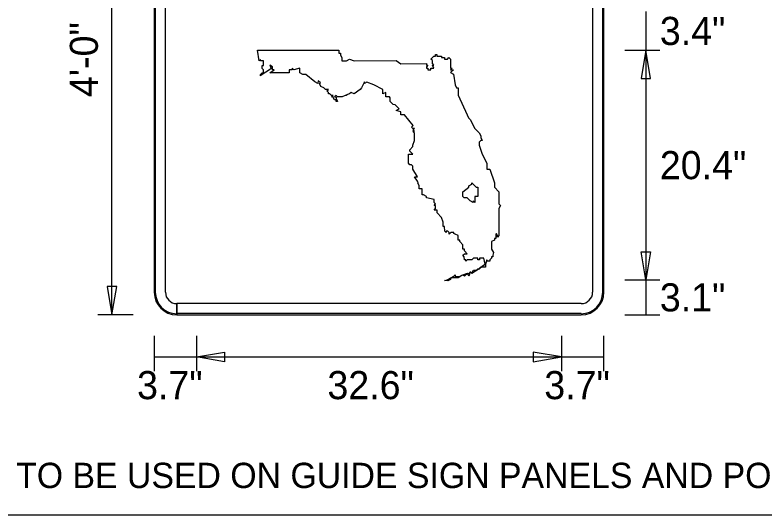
# Model space of a CAD drawing. Extents: x 17890628 to 17890844, y 17897693 to 17898031.
# Drawn here: x 17890808.4 to 17890826.19, y 17897976.3 to 17897988.15 of the extents above; entities that cross this region are included whole.
import ezdxf

# ---------------------------------------------------------------- set-up
doc = ezdxf.new("R2010")
doc.units = 0
for name, color, linetype in [('GSColorFill', 7, 'Continuous'), ('GSDims', 7, 'Continuous'), ('SheetLinesMisc2_dp', 7, 'Continuous')]:
    doc.layers.add(name, color=color, linetype=linetype)

msp = doc.modelspace()

# ---------------------------------------------------------------- linework, layer by layer
at = {"layer": 'GSColorFill'}
for p, q in [((17890811.701, 17897993.312), (17890811.701, 17897981.578)), ((17890811.701, 17897993.312), (17890811.701, 17897981.578)), ((17890811.701, 17897993.312), (17890811.701, 17897981.578)), ((17890811.728, 17897981.578), (17890811.728, 17897993.312)), ((17890811.968, 17897981.578), (17890811.968, 17897993.312)), ((17890822.101, 17897993.312), (17890822.101, 17897981.578)), ((17890822.341, 17897993.312), (17890822.341, 17897981.578)), ((17890822.368, 17897981.578), (17890822.368, 17897993.312)), ((17890822.368, 17897981.578), (17890822.368, 17897993.312)), ((17890822.368, 17897981.578), (17890822.368, 17897993.312)), ((17890814.153, 17897987.316), (17890816.084, 17897987.318)), ((17890814.189, 17897987.065), (17890814.153, 17897987.316)), ((17890816.084, 17897987.318), (17890816.085, 17897987.247)), ((17890816.085, 17897987.247), (17890816.12, 17897987.246)), ((17890816.12, 17897987.246), (17890816.12, 17897987.211)), ((17890816.12, 17897987.211), (17890816.156, 17897987.139)), ((17890818.266, 17897987.105), (17890818.337, 17897987.177)), ((17890818.337, 17897987.177), (17890818.373, 17897987.177)), ((17890818.373, 17897987.177), (17890818.373, 17897987.213)), ((17890818.373, 17897987.213), (17890818.409, 17897987.213)), ((17890818.409, 17897987.213), (17890818.409, 17897987.177)), ((17890818.409, 17897987.177), (17890818.516, 17897987.177)), ((17890818.516, 17897987.177), (17890818.516, 17897987.142)), ((17890814.225, 17897987.101), (17890814.189, 17897987.065)), ((17890814.224, 17897987.065), (17890814.225, 17897987.101)), ((17890814.296, 17897987.066), (17890814.224, 17897987.065)), ((17890814.296, 17897986.958), (17890814.296, 17897987.066)), ((17890816.156, 17897987.139), (17890816.156, 17897987.068)), ((17890816.156, 17897987.068), (17890816.263, 17897987.068)), ((17890816.263, 17897987.068), (17890816.335, 17897987.104)), ((17890816.335, 17897987.104), (17890816.443, 17897987.068)), ((17890816.443, 17897987.068), (17890817.444, 17897987.07)), ((17890817.444, 17897987.07), (17890817.55, 17897986.998)), ((17890817.55, 17897986.998), (17890818.159, 17897986.999)), ((17890818.159, 17897986.999), (17890818.159, 17897986.963)), ((17890818.302, 17897987.07), (17890818.266, 17897987.105)), ((17890818.302, 17897986.999), (17890818.302, 17897987.07)), ((17890818.337, 17897986.963), (17890818.302, 17897986.999)), ((17890818.516, 17897987.142), (17890818.588, 17897987.142)), ((17890818.588, 17897987.142), (17890818.588, 17897987.106)), ((17890818.588, 17897987.106), (17890818.659, 17897987.106)), ((17890818.659, 17897987.106), (17890818.695, 17897987.142)), ((17890818.695, 17897987.142), (17890818.731, 17897987.106)), ((17890818.731, 17897987.106), (17890818.731, 17897986.892)), ((17890814.261, 17897986.887), (17890814.26, 17897986.958)), ((17890814.26, 17897986.958), (17890814.296, 17897986.958)), ((17890814.297, 17897986.851), (17890814.261, 17897986.887)), ((17890814.439, 17897986.851), (17890814.261, 17897986.743)), ((17890814.297, 17897986.78), (17890814.297, 17897986.851)), ((17890814.475, 17897986.886), (17890814.439, 17897986.851)), ((17890814.51, 17897986.923), (17890814.44, 17897986.959)), ((17890814.44, 17897986.959), (17890814.475, 17897986.886)), ((17890814.44, 17897986.78), (17890814.547, 17897986.851)), ((17890814.511, 17897986.851), (17890814.51, 17897986.923)), ((17890814.547, 17897986.851), (17890814.511, 17897986.851)), ((17890814.976, 17897986.852), (17890814.904, 17897986.851)), ((17890814.904, 17897986.851), (17890814.905, 17897986.779)), ((17890815.012, 17897986.851), (17890814.976, 17897986.888)), ((17890814.976, 17897986.888), (17890814.976, 17897986.852)), ((17890815.155, 17897986.888), (17890815.012, 17897986.851)), ((17890815.155, 17897986.78), (17890815.155, 17897986.888)), ((17890818.159, 17897986.963), (17890818.195, 17897986.963)), ((17890818.195, 17897986.963), (17890818.159, 17897986.927)), ((17890818.159, 17897986.927), (17890818.159, 17897986.891)), ((17890818.159, 17897986.891), (17890818.195, 17897986.891)), ((17890818.195, 17897986.891), (17890818.194, 17897986.855)), ((17890818.194, 17897986.855), (17890818.266, 17897986.856)), ((17890818.266, 17897986.856), (17890818.266, 17897986.891)), ((17890818.266, 17897986.891), (17890818.337, 17897986.891)), ((17890818.337, 17897986.891), (17890818.302, 17897986.964)), ((17890818.302, 17897986.964), (17890818.337, 17897986.963)), ((17890818.731, 17897986.892), (17890818.767, 17897986.891)), ((17890818.767, 17897986.891), (17890818.731, 17897986.856)), ((17890818.731, 17897986.856), (17890818.803, 17897986.856)), ((17890818.803, 17897986.856), (17890818.731, 17897986.785)), ((17890814.225, 17897986.744), (17890814.261, 17897986.779)), ((17890814.225, 17897986.708), (17890814.225, 17897986.744)), ((17890814.261, 17897986.743), (17890814.225, 17897986.708)), ((17890814.261, 17897986.779), (17890814.297, 17897986.78)), ((17890814.905, 17897986.779), (17890814.44, 17897986.78)), ((17890815.227, 17897986.745), (17890815.155, 17897986.78)), ((17890815.298, 17897986.745), (17890815.227, 17897986.745)), ((17890815.513, 17897986.567), (17890815.298, 17897986.745)), ((17890818.731, 17897986.785), (17890818.803, 17897986.749)), ((17890818.803, 17897986.749), (17890818.839, 17897986.499)), ((17890815.585, 17897986.53), (17890815.513, 17897986.567)), ((17890815.588, 17897986.591), (17890815.585, 17897986.53)), ((17890815.644, 17897986.542), (17890815.588, 17897986.591)), ((17890815.62, 17897986.53), (17890815.644, 17897986.542)), ((17890815.656, 17897986.459), (17890815.62, 17897986.53)), ((17890815.728, 17897986.423), (17890815.656, 17897986.459)), ((17890816.693, 17897986.567), (17890816.622, 17897986.425)), ((17890816.693, 17897986.531), (17890816.693, 17897986.567)), ((17890816.744, 17897986.558), (17890816.693, 17897986.531)), ((17890816.908, 17897986.497), (17890816.744, 17897986.558)), ((17890817.123, 17897986.389), (17890816.908, 17897986.497)), ((17890818.839, 17897986.499), (17890818.875, 17897986.427)), ((17890815.763, 17897986.387), (17890815.728, 17897986.423)), ((17890815.834, 17897986.388), (17890815.763, 17897986.387)), ((17890815.799, 17897986.352), (17890815.834, 17897986.388)), ((17890815.835, 17897986.316), (17890815.799, 17897986.352)), ((17890815.836, 17897986.281), (17890815.835, 17897986.316)), ((17890815.87, 17897986.28), (17890815.836, 17897986.281)), ((17890815.907, 17897986.245), (17890815.87, 17897986.28)), ((17890816.336, 17897986.281), (17890816.264, 17897986.257)), ((17890816.371, 17897986.317), (17890816.336, 17897986.281)), ((17890816.443, 17897986.281), (17890816.371, 17897986.317)), ((17890816.587, 17897986.389), (17890816.443, 17897986.281)), ((17890816.622, 17897986.425), (17890816.587, 17897986.389)), ((17890817.123, 17897986.283), (17890817.123, 17897986.389)), ((17890817.194, 17897986.318), (17890817.123, 17897986.283)), ((17890817.194, 17897986.211), (17890817.194, 17897986.318)), ((17890818.875, 17897986.427), (17890818.911, 17897986.427)), ((17890818.911, 17897986.427), (17890818.911, 17897986.248)), ((17890815.906, 17897986.209), (17890815.943, 17897986.245)), ((17890815.942, 17897986.209), (17890815.906, 17897986.209)), ((17890815.943, 17897986.245), (17890815.907, 17897986.245)), ((17890815.979, 17897986.138), (17890815.942, 17897986.209)), ((17890816.014, 17897986.244), (17890815.978, 17897986.209)), ((17890815.978, 17897986.209), (17890816.014, 17897986.208)), ((17890816.014, 17897986.137), (17890815.979, 17897986.138)), ((17890816.049, 17897986.209), (17890816.014, 17897986.244)), ((17890816.014, 17897986.208), (17890816.014, 17897986.173)), ((17890816.014, 17897986.173), (17890816.049, 17897986.102)), ((17890816.014, 17897986.105), (17890816.014, 17897986.137)), ((17890816.049, 17897986.102), (17890816.014, 17897986.105)), ((17890816.157, 17897986.21), (17890816.049, 17897986.209)), ((17890816.229, 17897986.245), (17890816.157, 17897986.21)), ((17890816.265, 17897986.245), (17890816.229, 17897986.245)), ((17890816.264, 17897986.257), (17890816.265, 17897986.245)), ((17890817.285, 17897986.21), (17890817.194, 17897986.211)), ((17890817.302, 17897986.191), (17890817.285, 17897986.21)), ((17890817.302, 17897986.103), (17890817.302, 17897986.191)), ((17890817.374, 17897986.032), (17890817.302, 17897986.103)), ((17890818.911, 17897986.248), (17890819.126, 17897985.784)), ((17890817.418, 17897986.024), (17890817.374, 17897986.032)), ((17890817.516, 17897985.925), (17890817.418, 17897986.024)), ((17890817.445, 17897985.888), (17890817.516, 17897985.925)), ((17890817.552, 17897985.853), (17890817.445, 17897985.888)), ((17890817.552, 17897985.782), (17890817.552, 17897985.853)), ((17890817.638, 17897985.782), (17890817.552, 17897985.782)), ((17890817.841, 17897985.534), (17890817.638, 17897985.782)), ((17890819.126, 17897985.784), (17890819.161, 17897985.712)), ((17890819.161, 17897985.712), (17890819.198, 17897985.676)), ((17890819.198, 17897985.676), (17890819.306, 17897985.462)), ((17890817.803, 17897985.496), (17890817.841, 17897985.534)), ((17890817.838, 17897985.461), (17890817.803, 17897985.496)), ((17890817.873, 17897985.459), (17890817.838, 17897985.461)), ((17890817.839, 17897985.425), (17890817.873, 17897985.459)), ((17890817.875, 17897985.389), (17890817.839, 17897985.425)), ((17890817.875, 17897985.353), (17890817.839, 17897985.389)), ((17890817.839, 17897985.389), (17890817.845, 17897985.388)), ((17890817.845, 17897985.388), (17890817.875, 17897985.389)), ((17890819.306, 17897985.462), (17890819.413, 17897985.355)), ((17890817.875, 17897985.174), (17890817.875, 17897985.353)), ((17890819.413, 17897985.355), (17890819.448, 17897985.284)), ((17890819.448, 17897985.284), (17890819.448, 17897985.247)), ((17890819.448, 17897985.247), (17890819.484, 17897985.176)), ((17890817.768, 17897984.959), (17890817.84, 17897985.031)), ((17890817.839, 17897985.066), (17890817.875, 17897985.174)), ((17890817.84, 17897985.031), (17890817.839, 17897985.066)), ((17890819.449, 17897985.176), (17890819.412, 17897985.14)), ((17890819.412, 17897985.14), (17890819.412, 17897985.069)), ((17890819.412, 17897985.069), (17890819.485, 17897984.854)), ((17890819.484, 17897985.176), (17890819.449, 17897985.176)), ((17890817.733, 17897984.638), (17890817.732, 17897984.852)), ((17890817.732, 17897984.852), (17890817.84, 17897984.852)), ((17890817.768, 17897984.924), (17890817.768, 17897984.959)), ((17890817.84, 17897984.852), (17890817.768, 17897984.924)), ((17890819.485, 17897984.854), (17890819.592, 17897984.64)), ((17890817.768, 17897984.601), (17890817.733, 17897984.638)), ((17890817.804, 17897984.602), (17890817.768, 17897984.601)), ((17890817.84, 17897984.566), (17890817.804, 17897984.602)), ((17890817.84, 17897984.495), (17890817.84, 17897984.566)), ((17890817.948, 17897984.315), (17890817.84, 17897984.495)), ((17890819.592, 17897984.64), (17890819.592, 17897984.496)), ((17890819.592, 17897984.496), (17890819.664, 17897984.497)), ((17890819.664, 17897984.497), (17890819.771, 17897984.174)), ((17890817.948, 17897984.209), (17890817.876, 17897984.316)), ((17890817.876, 17897984.316), (17890817.948, 17897984.315)), ((17890817.965, 17897984.156), (17890817.947, 17897984.173)), ((17890817.947, 17897984.173), (17890817.96, 17897984.173)), ((17890817.96, 17897984.173), (17890817.948, 17897984.209)), ((17890817.984, 17897984.101), (17890817.965, 17897984.156)), ((17890819.771, 17897984.174), (17890819.772, 17897984.068)), ((17890817.984, 17897984.029), (17890817.984, 17897984.101)), ((17890818.056, 17897984.029), (17890817.984, 17897984.029)), ((17890818.056, 17897983.887), (17890818.056, 17897984.029)), ((17890819.772, 17897984.068), (17890819.879, 17897983.961)), ((17890819.879, 17897983.961), (17890819.88, 17897983.674)), ((17890818.092, 17897983.887), (17890818.056, 17897983.887)), ((17890818.163, 17897983.851), (17890818.092, 17897983.887)), ((17890818.163, 17897983.815), (17890818.163, 17897983.851)), ((17890818.341, 17897983.78), (17890818.163, 17897983.815)), ((17890818.342, 17897983.708), (17890818.341, 17897983.78)), ((17890818.341, 17897983.637), (17890818.377, 17897983.673)), ((17890818.377, 17897983.637), (17890818.341, 17897983.637)), ((17890818.377, 17897983.673), (17890818.342, 17897983.708)), ((17890818.378, 17897983.566), (17890818.377, 17897983.637)), ((17890819.88, 17897983.674), (17890819.915, 17897983.638)), ((17890819.915, 17897983.638), (17890819.88, 17897983.567)), ((17890818.342, 17897983.529), (17890818.378, 17897983.566)), ((17890818.413, 17897983.529), (17890818.342, 17897983.529)), ((17890818.414, 17897983.459), (17890818.413, 17897983.529)), ((17890818.521, 17897983.351), (17890818.414, 17897983.459)), ((17890819.88, 17897983.567), (17890819.881, 17897982.923)), ((17890818.557, 17897983.244), (17890818.521, 17897983.351)), ((17890818.557, 17897983.136), (17890818.557, 17897983.244)), ((17890818.592, 17897983.136), (17890818.557, 17897983.136)), ((17890818.593, 17897983.029), (17890818.592, 17897983.136)), ((17890818.629, 17897982.994), (17890818.593, 17897983.029)), ((17890818.665, 17897983.029), (17890818.629, 17897983.029)), ((17890818.629, 17897983.029), (17890818.629, 17897982.994)), ((17890818.7, 17897982.994), (17890818.665, 17897983.029)), ((17890818.736, 17897982.994), (17890818.7, 17897982.958)), ((17890818.7, 17897982.958), (17890818.7, 17897982.994)), ((17890818.808, 17897982.994), (17890818.736, 17897982.994)), ((17890818.807, 17897982.976), (17890818.808, 17897982.994)), ((17890818.843, 17897982.958), (17890818.807, 17897982.976)), ((17890818.915, 17897982.922), (17890818.843, 17897982.958)), ((17890818.915, 17897982.815), (17890818.915, 17897982.922)), ((17890819.821, 17897982.971), (17890819.809, 17897982.959)), ((17890819.809, 17897982.959), (17890819.809, 17897982.852)), ((17890819.845, 17897982.924), (17890819.821, 17897982.971)), ((17890819.845, 17897982.887), (17890819.845, 17897982.924)), ((17890819.881, 17897982.923), (17890819.845, 17897982.887)), ((17890818.951, 17897982.815), (17890818.915, 17897982.815)), ((17890818.951, 17897982.78), (17890818.951, 17897982.815)), ((17890819.022, 17897982.707), (17890818.951, 17897982.78)), ((17890819.773, 17897982.816), (17890819.702, 17897982.78)), ((17890819.702, 17897982.78), (17890819.702, 17897982.601)), ((17890819.774, 17897982.851), (17890819.773, 17897982.816)), ((17890819.809, 17897982.852), (17890819.774, 17897982.851)), ((17890819.022, 17897982.6), (17890819.022, 17897982.707)), ((17890819.059, 17897982.599), (17890819.022, 17897982.6)), ((17890819.059, 17897982.565), (17890819.059, 17897982.599)), ((17890819.13, 17897982.493), (17890819.059, 17897982.565)), ((17890819.702, 17897982.601), (17890819.755, 17897982.523)), ((17890819.023, 17897982.458), (17890819.059, 17897982.494)), ((17890819.058, 17897982.422), (17890819.023, 17897982.458)), ((17890819.059, 17897982.35), (17890819.058, 17897982.422)), ((17890819.059, 17897982.494), (17890819.13, 17897982.493)), ((17890819.273, 17897982.386), (17890819.238, 17897982.351)), ((17890819.38, 17897982.386), (17890819.273, 17897982.386)), ((17890819.38, 17897982.351), (17890819.38, 17897982.386)), ((17890819.524, 17897982.386), (17890819.416, 17897982.386)), ((17890819.416, 17897982.386), (17890819.416, 17897982.351)), ((17890819.556, 17897982.244), (17890819.524, 17897982.386)), ((17890819.703, 17897982.386), (17890819.666, 17897982.352)), ((17890819.738, 17897982.423), (17890819.701, 17897982.422)), ((17890819.701, 17897982.422), (17890819.703, 17897982.386)), ((17890819.755, 17897982.523), (17890819.738, 17897982.458)), ((17890819.738, 17897982.458), (17890819.738, 17897982.423)), ((17890819.095, 17897982.35), (17890819.059, 17897982.35)), ((17890819.13, 17897982.35), (17890819.095, 17897982.315)), ((17890819.095, 17897982.315), (17890819.095, 17897982.35)), ((17890819.238, 17897982.351), (17890819.13, 17897982.35)), ((17890819.416, 17897982.351), (17890819.38, 17897982.351)), ((17890819.452, 17897982.172), (17890819.488, 17897982.208)), ((17890819.488, 17897982.208), (17890819.556, 17897982.244)), ((17890819.56, 17897982.244), (17890819.559, 17897982.172)), ((17890819.595, 17897982.349), (17890819.56, 17897982.244)), ((17890819.595, 17897982.314), (17890819.595, 17897982.349)), ((17890819.666, 17897982.315), (17890819.595, 17897982.314)), ((17890819.666, 17897982.352), (17890819.666, 17897982.315)), ((17890819.023, 17897981.993), (17890819.131, 17897982.029)), ((17890819.132, 17897982.027), (17890819.059, 17897981.957)), ((17890819.131, 17897982.029), (17890819.167, 17897982.028)), ((17890819.166, 17897981.957), (17890819.132, 17897982.027)), ((17890819.2, 17897982.06), (17890819.166, 17897981.957)), ((17890819.167, 17897982.028), (17890819.202, 17897982.064)), ((17890819.238, 17897982.028), (17890819.2, 17897982.06)), ((17890819.202, 17897982.064), (17890819.238, 17897982.03)), ((17890819.412, 17897982.134), (17890819.238, 17897982.028)), ((17890819.238, 17897982.03), (17890819.273, 17897982.1)), ((17890819.273, 17897982.1), (17890819.345, 17897982.1)), ((17890819.345, 17897982.1), (17890819.381, 17897982.136)), ((17890819.381, 17897982.136), (17890819.415, 17897982.138)), ((17890819.465, 17897982.172), (17890819.412, 17897982.134)), ((17890819.415, 17897982.138), (17890819.452, 17897982.172)), ((17890819.559, 17897982.172), (17890819.465, 17897982.172)), ((17890818.59, 17897981.861), (17890818.63, 17897981.868)), ((17890818.667, 17897981.851), (17890818.59, 17897981.861)), ((17890818.63, 17897981.868), (17890818.671, 17897981.881)), ((17890818.696, 17897981.868), (17890818.667, 17897981.851)), ((17890818.671, 17897981.881), (17890818.738, 17897981.921)), ((17890818.729, 17897981.882), (17890818.696, 17897981.868)), ((17890818.738, 17897981.92), (17890818.729, 17897981.882)), ((17890818.738, 17897981.921), (17890818.808, 17897981.957)), ((17890818.809, 17897981.921), (17890818.738, 17897981.92)), ((17890818.808, 17897981.957), (17890818.844, 17897981.992)), ((17890818.916, 17897981.922), (17890818.809, 17897981.921)), ((17890818.844, 17897981.992), (17890818.844, 17897981.956)), ((17890818.844, 17897981.956), (17890818.951, 17897981.956)), ((17890818.997, 17897981.973), (17890818.916, 17897981.922)), ((17890818.951, 17897981.956), (17890819.023, 17897981.993)), ((17890819.031, 17897981.985), (17890818.997, 17897981.973)), ((17890819.059, 17897981.957), (17890819.031, 17897981.985)), ((17890812.234, 17897981.045), (17890812.234, 17897981.312)), ((17890821.835, 17897981.312), (17890812.237, 17897981.312)), ((17890812.237, 17897981.312), (17890812.237, 17897981.045)), ((17890812.234, 17897981.045), (17890812.234, 17897981.072)), ((17890812.234, 17897981.045), (17890821.835, 17897981.045)), ((17890821.835, 17897981.072), (17890812.235, 17897981.072)), ((17890812.235, 17897981.072), (17890812.235, 17897981.045)), ((17890812.235, 17897981.045), (17890821.835, 17897981.045)), ((17890812.237, 17897981.045), (17890821.835, 17897981.045))]:
    msp.add_line(p, q, dxfattribs=at)
msp.add_lwpolyline([(17890819.235, 17897984.174), (17890819.342, 17897984.067), (17890819.378, 17897984.067), (17890819.379, 17897983.852), (17890819.307, 17897983.853), (17890819.307, 17897983.71), (17890819.272, 17897983.745), (17890819.271, 17897983.709), (17890819.201, 17897983.745), (17890819.128, 17897983.816), (17890819.058, 17897983.816), (17890819.021, 17897983.852), (17890819.022, 17897983.96), (17890819.164, 17897984.067), (17890819.164, 17897984.103), (17890819.235, 17897984.139)], close=True, dxfattribs=at)
for centre, radius, start, end in [((17890812.234, 17897981.578), 0.533, 180, 270), ((17890812.234, 17897981.578), 0.533, 180, 270), ((17890812.234, 17897981.578), 0.533, 180, 270), ((17890812.234, 17897981.578), 0.507, 180, 270), ((17890812.234, 17897981.578), 0.267, 180, 270), ((17890821.835, 17897981.578), 0.533, 270, 0), ((17890821.835, 17897981.578), 0.533, 270, 0), ((17890821.835, 17897981.578), 0.267, 270, 360), ((17890821.835, 17897981.578), 0.533, 270, 0), ((17890821.835, 17897981.578), 0.507, 270, 0)]:
    msp.add_arc(centre, radius, start, end, dxfattribs=at)
at = {"layer": 'GSDims'}
for p, q in [((17890810.698, 17897981.045), (17890810.698, 17897993.846)), ((17890823.365, 17897988.233), (17890823.365, 17897987.316)), ((17890822.865, 17897987.316), (17890823.698, 17897987.316)), ((17890822.865, 17897987.316), (17890823.698, 17897987.316)), ((17890823.365, 17897987.316), (17890823.365, 17897981.872)), ((17890822.865, 17897981.872), (17890823.698, 17897981.872)), ((17890822.865, 17897981.872), (17890823.698, 17897981.872)), ((17890823.365, 17897981.872), (17890823.365, 17897981.045)), ((17890811.198, 17897981.045), (17890810.365, 17897981.045)), ((17890822.865, 17897981.045), (17890823.698, 17897981.045)), ((17890811.698, 17897980.545), (17890811.698, 17897979.712)), ((17890812.703, 17897980.545), (17890812.703, 17897979.712)), ((17890812.703, 17897980.545), (17890812.703, 17897979.712)), ((17890821.361, 17897980.545), (17890821.361, 17897979.712)), ((17890821.361, 17897980.545), (17890821.361, 17897979.712)), ((17890822.365, 17897980.545), (17890822.365, 17897979.712)), ((17890811.698, 17897980.045), (17890812.703, 17897980.045)), ((17890812.703, 17897980.045), (17890821.361, 17897980.045)), ((17890821.361, 17897980.045), (17890822.365, 17897980.045))]:
    msp.add_line(p, q, dxfattribs=at)
for points in [[(17890823.365, 17897987.316), (17890823.254, 17897986.649), (17890823.476, 17897986.649)], [(17890823.365, 17897981.872), (17890823.254, 17897982.538), (17890823.476, 17897982.538)], [(17890810.698, 17897981.045), (17890810.81, 17897981.712), (17890810.587, 17897981.712)], [(17890812.703, 17897980.045), (17890813.369, 17897980.156), (17890813.369, 17897979.934)], [(17890821.361, 17897980.045), (17890820.694, 17897980.156), (17890820.694, 17897979.934)]]:
    msp.add_lwpolyline(points, close=True, dxfattribs=at)
at = {"layer": 'SheetLinesMisc2_dp'}
msp.add_line((17890793.11, 17897976.3), (17890838.594, 17897976.3), dxfattribs=at)

# ---------------------------------------------------------------- texts
at = {"layer": 'GSDims'}
for s, height, p in [('3.4"', 0.6667, (17890823.698, 17897987.441)), ('20.4"', 0.6667, (17890823.698, 17897984.26)), ('3.1"', 0.6667, (17890823.698, 17897981.125)), ('3.7"', 0.6667, (17890811.293, 17897979.045)), ('32.6"', 0.6667, (17890815.81, 17897979.045)), ('3.7"', 0.6667, (17890820.956, 17897979.045)), ('TO BE USED ON GUIDE SIGN PANELS AND POST INTERCHANGE SIGNING ', 0.6, (17890808.424, 17897976.938))]:
    msp.add_text(s, height=height, dxfattribs=at).set_placement(p)
msp.add_text('4\'-0"', height=0.6667, rotation=90, dxfattribs=at).set_placement((17890810.365, 17897986.207))

doc.saveas('drawing.dxf')
